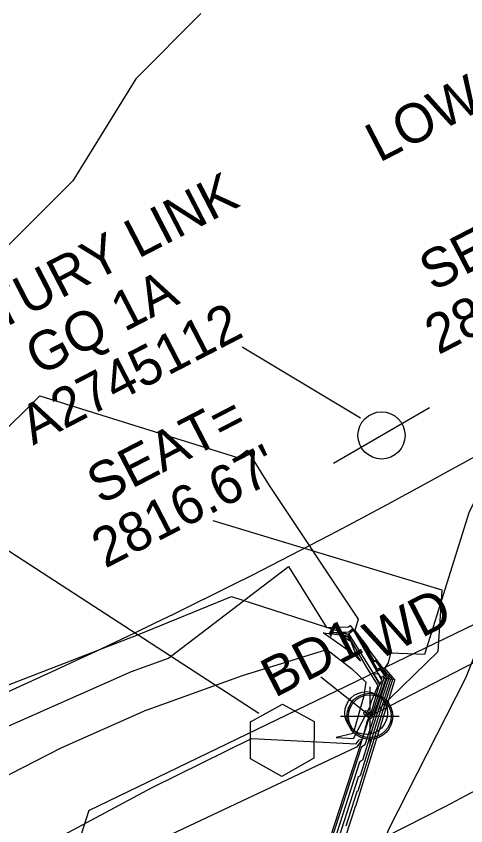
# Model space of a CAD drawing. Extents: x 1284446 to 1285480, y 969739 to 970628.
# Drawn here: x 1284857.4 to 1284903.3, y 970190.8 to 970273.5 of the extents above; entities that cross this region are included whole.
import ezdxf

# ---------------------------------------------------------------- set-up
doc = ezdxf.new("R2010")
doc.units = 0
for name, color, linetype in [('Cogo Default Point CELL', 7, 'Continuous'), ('CTL Primary Horizontal and Vertical CELL', 7, 'Continuous'), ('CTL Primary Horizontal and Vertical Leader', 7, 'Continuous'), ('Default', 7, 'Continuous'), ('Exist Horizontal Alignment', 7, 'Continuous'), ('Exist Hydro Jurisdictional Stream or Body of Water', 7, 'Continuous'), ('Exist Other Culture Fence Line', 7, 'Continuous'), ('Exist Other Culture Located Object CELL', 7, 'Continuous'), ('Exist Other Culture Located Object Leader', 7, 'Continuous'), ('Exist Other Culture Located Object Text', 7, 'Continuous'), ('Exist Other Culture Sign CELL', 7, 'Continuous'), ('Exist Right of Way Line', 7, 'Continuous'), ('Exist Roads EOP', 7, 'Continuous'), ('Exist Structure Major Bridge WW', 7, 'Continuous'), ('Exist Structure Major Bridge WW Text', 7, 'Continuous'), ('Exist Structure Major Deck Tunnel Box Culvert', 7, 'Continuous'), ('Exist Structure Minor Head and End Wall', 7, 'Continuous'), ('Exist Utilities Other Located Object Text', 7, 'Continuous'), ('Exist Utilities Telephone Pole CELL', 7, 'Continuous'), ('Exist Utilities Telephone Pole Leader', 7, 'Continuous'), ('Exist Utilities Telephone Pole Text', 7, 'Continuous')]:
    doc.layers.add(name, color=color, linetype=linetype)

msp = doc.modelspace()

# ---------------------------------------------------------------- linework, layer by layer
at = {"layer": 'Cogo Default Point CELL'}
for points in [[(1284893.517, 970205.025), (1284893.517, 970202.025)], [(1284890.517, 970202.025), (1284893.517, 970202.025)], [(1284893.517, 970202.025), (1284896.517, 970202.025)], [(1284893.517, 970202.025), (1284893.517, 970199.025)]]:
    msp.add_lwpolyline(points, dxfattribs=at)
msp.add_circle((1284893.517, 970202.025), 2.344, dxfattribs=at)
at = {"layer": 'CTL Primary Horizontal and Vertical CELL'}
msp.add_line((1284884.582, 970199.574), (1284884.582, 970199.574), dxfattribs=at)
msp.add_lwpolyline([(1284881.351, 970201.446), (1284884.601, 970203.258), (1284887.851, 970201.471), (1284887.801, 970197.746), (1284884.551, 970195.858), (1284881.351, 970197.671)], close=True, dxfattribs=at)
at = {"layer": 'CTL Primary Horizontal and Vertical Leader'}
msp.add_line((1284882.183, 970202.312), (1284810.437, 970248.874), dxfattribs=at)
at = {"layer": 'Default'}
for points in [[(1284876.272, 970273.741), (1284869.622, 970267.088), (1284863.193, 970256.674), (1284853.546, 970247.046)], [(1284917.725, 970251.824), (1284912.221, 970241.257), (1284909.188, 970233.769), (1284903.658, 970222.875), (1284899.099, 970208.331), (1284895.642, 970208.459), (1284895.374, 970207.464), (1284895.028, 970206.937), (1284895.408, 970206.436), (1284895.414, 970206.433), (1284896.05, 970205.718), (1284895.957, 970205.436), (1284895.886, 970205.226), (1284892.06, 970192.808), (1284892.035, 970192.791), (1284891.792, 970192.037), (1284885.68, 970173.557)], [(1284845.899, 970220.914), (1284859.843, 970234.711), (1284880.019, 970228.434), (1284880.991, 970229.177), (1284883.225, 970225.58), (1284892.313, 970211.915), (1284891.975, 970210.767), (1284893.206, 970209.16), (1284893.61, 970208.481), (1284893.625, 970208.528), (1284895.303, 970206.313), (1284895.354, 970206.291), (1284895.843, 970205.74), (1284895.499, 970204.708), (1284895.241, 970203.935), (1284892.296, 970194.379), (1284892.182, 970194.301), (1284891.051, 970190.792)], [(1284844.67, 970195.742), (1284869.181, 970206.599), (1284869.198, 970206.593), (1284872.964, 970207.951), (1284873.007, 970207.977), (1284885.228, 970217.319), (1284889.109, 970211.068), (1284891.352, 970211.157), (1284891.524, 970211.29), (1284892.636, 970209.838), (1284893.978, 970207.584), (1284894.025, 970207.738), (1284895.197, 970206.19), (1284895.293, 970206.149), (1284895.636, 970205.763), (1284895.041, 970203.98), (1284894.596, 970202.644), (1284892.533, 970195.95), (1284892.33, 970195.812), (1284890.31, 970189.546)], [(1284843.812, 970189.472), (1284862.011, 970198.788), (1284870.769, 970202.668), (1284870.775, 970202.666), (1284880.515, 970206.177), (1284889.125, 970208.841), (1284891.693, 970206.87), (1284893.105, 970205.485), (1284892.871, 970203.963), (1284891.816, 970200.241), (1284890.07, 970199.852), (1284891.856, 970199.761), (1284891.872, 970199.783), (1284891.89, 970199.785), (1284891.914, 970199.882), (1284893.5, 970202.94), (1284893.679, 970203.547), (1284894.376, 970205.173), (1284893.306, 970206.83), (1284891.553, 970209.855), (1284891.356, 970210.353), (1284889.475, 970210.566), (1284891.361, 970210.64), (1284891.744, 970210.937), (1284892.066, 970210.517), (1284894.345, 970206.686), (1284894.425, 970206.948), (1284895.092, 970206.068), (1284895.232, 970206.007), (1284895.429, 970205.786), (1284894.583, 970203.251), (1284893.95, 970201.353), (1284892.769, 970197.521), (1284892.477, 970197.322), (1284889.569, 970188.301)], [(1284888.742, 970210.516), (1284891.335, 970210.223), (1284891.977, 970208.601), (1284892.209, 970208.201), (1284892.568, 970207.645), (1284891.996, 970208.206), (1284891.083, 970208.907), (1284888.742, 970210.516)], [(1284891.469, 970209.705), (1284891.315, 970210.093), (1284890.822, 970210.149), (1284891.469, 970209.705)], [(1284858.911, 970188.117), (1284871.311, 970194.739), (1284881.441, 970199.739), (1284892.124, 970199.195), (1284892.429, 970199.624), (1284892.783, 970199.665), (1284893.263, 970201.583), (1284893.648, 970202.327), (1284894.451, 970205.039), (1284894.54, 970205.247), (1284894.403, 970205.459), (1284893.896, 970206.335), (1284894.263, 970206.379), (1284894.352, 970206.395), (1284894.713, 970205.788), (1284894.825, 970206.158), (1284894.987, 970205.945), (1284895.172, 970205.865), (1284895.221, 970205.809), (1284894.125, 970202.523), (1284893.305, 970200.063), (1284893.006, 970199.092), (1284892.624, 970198.832), (1284888.828, 970187.055)]]:
    msp.add_lwpolyline(points, dxfattribs=at)
at = {"layer": 'Exist Horizontal Alignment'}
msp.add_arc((1284607.883, 970757.202), 636.05, 292.002785, 305.452776, dxfattribs=at)
at = {"layer": 'Exist Hydro Jurisdictional Stream or Body of Water'}
msp.add_lwpolyline([(1284873.191, 970156.896), (1284883.514, 970166.483), (1284889.938, 970172.965), (1284895.436, 970190.434), (1284903.301, 970205.953), (1284913.733, 970232.003), (1284923.66, 970254.249), (1284941.007, 970272.574), (1284958.155, 970292.526), (1284979.255, 970313.173), (1284998.608, 970327.405), (1285021.767, 970343.415), (1285038.635, 970357.962), (1285060.694, 970382.427), (1285077.066, 970403.68), (1285083.989, 970417.362), (1285093.674, 970433.198), (1285120.383, 970455.771)], dxfattribs=at)
at = {"layer": 'Exist Other Culture Fence Line'}
msp.add_lwpolyline([(1284798.036, 970188.583), (1284802.023, 970182.243), (1284816.974, 970188.805), (1284845.254, 970200.837), (1284869.92, 970210.375), (1284879.4, 970214.228), (1284891.22, 970210.434)], dxfattribs=at)
at = {"layer": 'Exist Other Culture Located Object CELL'}
for radius in [2.18, 0.24]:
    msp.add_circle((1284893.517, 970202.025), radius, dxfattribs=at)
at = {"layer": 'Exist Other Culture Located Object Leader'}
msp.add_line((1284893.431, 970202.114), (1284888.525, 970206.01), dxfattribs=at)
msp.add_lwpolyline([(1284894.322, 970202.654), (1284900.493, 970208.627), (1284900.889, 970214.88), (1284877.51, 970221.969)], dxfattribs=at)
at = {"layer": 'Exist Other Culture Located Object Text'}
for q in [(1284921.603, 970219.816), (1284852.275, 970153.011)]:
    msp.add_line((1284864.825, 970192.389), q, dxfattribs=at)
at = {"layer": 'Exist Other Culture Sign CELL'}
for radius in [2.18, 0.24]:
    msp.add_circle((1284893.151, 970202.348), radius, dxfattribs=at)
at = {"layer": 'Exist Right of Way Line'}
for radius in [606.05, 666.05]:
    msp.add_arc((1284607.883, 970757.202), radius, 292.002785, 305.452776, dxfattribs=at)
at = {"layer": 'Exist Roads EOP'}
msp.add_lwpolyline([(1284588.171, 970073.973), (1284609.91, 970082.543), (1284630.168, 970090.653), (1284654.441, 970100.496), (1284678.032, 970109.926), (1284701.915, 970119.24), (1284725.507, 970128.631), (1284750.963, 970139.344), (1284775.609, 970149.46), (1284801.885, 970159.765), (1284826.13, 970169.581), (1284850.018, 970179.49), (1284870.964, 970188.879), (1284892.256, 970198.918), (1284892.634, 970199.462)], dxfattribs=at)
at = {"layer": 'Exist Structure Major Bridge WW'}
msp.add_lwpolyline([(1284894.564, 970205.258), (1284894.747, 970205.705), (1284891.834, 970210.793), (1284891.365, 970210.411), (1284894.564, 970205.258)], dxfattribs=at)
at = {"layer": 'Exist Structure Major Deck Tunnel Box Culvert'}
msp.add_lwpolyline([(1284893.517, 970202.025), (1284916.141, 970213.687), (1284905.121, 970179.642), (1284882.421, 970167.887), (1284893.517, 970202.025)], dxfattribs=at)
at = {"layer": 'Exist Structure Minor Head and End Wall'}
for points in [[(1284894.953, 970205.906), (1284893.705, 970202.159)], [(1284893.976, 970202.293), (1284895.151, 970205.817), (1284894.953, 970205.906)]]:
    msp.add_lwpolyline(points, dxfattribs=at)
at = {"layer": 'Exist Utilities Telephone Pole CELL'}
for p, q in [((1284889.8, 970227.838), (1284899.613, 970233.516)), ((1284894.712, 970230.68), (1284894.712, 970230.68))]:
    msp.add_line(p, q, dxfattribs=at)
msp.add_circle((1284894.712, 970230.68), 2.407, dxfattribs=at)
at = {"layer": 'Exist Utilities Telephone Pole Leader'}
msp.add_line((1284892.559, 970232.443), (1284880.475, 970239.692), dxfattribs=at)

# ---------------------------------------------------------------- texts
at = {"layer": 'Exist Other Culture Located Object Text'}
for s, p in [('SEAT=', (1284899.945, 970245.325)), ("2816.78'", (1284900.517, 970238.866)), ('SEAT=', (1284866.019, 970223.568)), ("2816.67'", (1284866.506, 970217.066)), ('BD1', (1284883.8, 970203.861))]:
    msp.add_text(s, height=4, rotation=27.32349, dxfattribs=at).set_placement(p)
at = {"layer": 'Exist Structure Major Bridge WW Text'}
msp.add_text('WD', height=4, rotation=27.32349, dxfattribs=at).set_placement((1284894.32, 970207.651))
at = {"layer": 'Exist Utilities Other Located Object Text'}
msp.add_text("LOW WIRE=2833.21'", height=4, rotation=27.32349, dxfattribs=at).set_placement((1284894.473, 970258.484))
at = {"layer": 'Exist Utilities Telephone Pole Text'}
for s, p in [('CENTURY LINK', (1284845.575, 970236.14)), ('GQ 1A', (1284859.746, 970236.708)), ('A2745112', (1284859.142, 970229.643))]:
    msp.add_text(s, height=4, rotation=27.32349, dxfattribs=at).set_placement(p)

doc.saveas('drawing.dxf')
